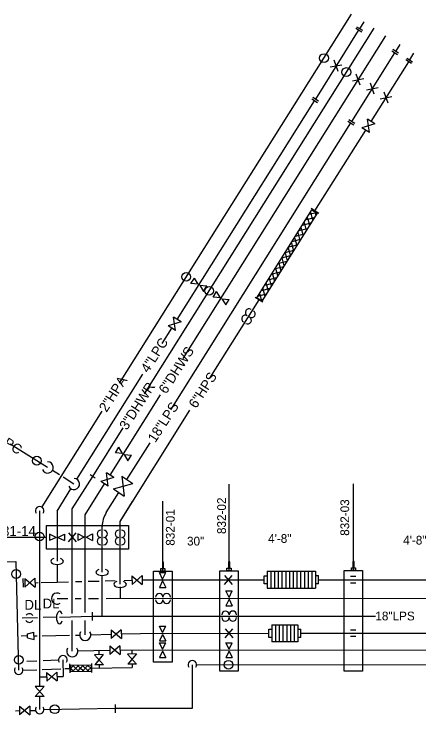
# Model space of a CAD drawing. Extents: x 9888 to 10178, y 10284 to 10314.
# Drawn here: x 9944.72 to 9960.12, y 10286.96 to 10313.63 of the extents above; entities that cross this region are included whole.
import ezdxf

# ---------------------------------------------------------------- set-up
doc = ezdxf.new("R2010")
doc.units = 0
for name, color, linetype in [('Level 51', 7, 'Continuous'), ('Level 52', 7, 'Continuous'), ('Level 53', 7, 'Continuous'), ('Level 54', 7, 'Continuous'), ('Level 55', 7, 'Continuous'), ('M-EQPM-N', 7, 'Continuous'), ('M-PROC-PIPE', 7, 'Continuous'), ('M-STEM-CONP', 7, 'Continuous'), ('M-STEM-CONP-N', 7, 'Continuous'), ('P-CMPA-PIPE', 7, 'Continuous'), ('P-CMPA-PIPE-N', 7, 'Continuous'), ('P-DOMW-HPIP', 7, 'Continuous'), ('P-DOMW-HPIP-N', 7, 'Continuous')]:
    doc.layers.add(name, color=color, linetype=linetype)

msp = doc.modelspace()

# ---------------------------------------------------------------- linework, layer by layer
at = {"layer": 'Level 51'}
for p, q in [((9956.19, 10310.392), (9957.823, 10312.996)), ((9957.942, 10312.935), (9957.721, 10313.073)), ((9957.979, 10312.994), (9957.758, 10313.132)), ((9956.745, 10311.614), (9957.186, 10311.696)), ((9957.04, 10311.444), (9956.891, 10311.866)), ((9956.043, 10310.403), (9956.264, 10310.264)), ((9956.08, 10310.462), (9956.3, 10310.323)), ((9951.069, 10301.918), (9950.786, 10302.096)), ((9950.862, 10301.59), (9950.786, 10302.096)), ((9951.069, 10301.918), (9950.579, 10301.767)), ((9950.35, 10301.088), (9950.721, 10301.678)), ((9950.862, 10301.59), (9950.579, 10301.767)), ((9947.113, 10295.926), (9949.622, 10299.926)), ((9945.996, 10296.374), (9944.576, 10297.265)), ((9946.444, 10296.094), (9946.178, 10296.26)), ((9946.999, 10295.745), (9946.593, 10296)), ((9946.355, 10294.718), (9946.885, 10295.564)), ((9946.355, 10294.718), (9946.355, 10292.806)), ((9946.319, 10293.716), (9946.071, 10293.84)), ((9946.071, 10293.84), (9946.071, 10293.592)), ((9946.389, 10293.716), (9946.636, 10293.84)), ((9946.636, 10293.84), (9946.636, 10293.592)), ((9946.319, 10293.716), (9946.071, 10293.592)), ((9946.389, 10293.716), (9946.636, 10293.592)), ((9946.355, 10292.686), (9946.355, 10292.012)), ((9949.203, 10292.252), (9949.209, 10291.918)), ((9949.203, 10292.252), (9949.597, 10291.924)), ((9949.592, 10292.258), (9949.209, 10291.918)), ((9949.592, 10292.258), (9949.597, 10291.924)), ((9950.37, 10292.128), (9950.246, 10292.376)), ((9950.246, 10292.376), (9950.494, 10292.376)), ((9950.37, 10292.128), (9950.494, 10292.376)), ((9952.72, 10291.926), (9953.012, 10292.266)), ((9952.72, 10292.266), (9953.012, 10291.926)), ((9954.229, 10291.943), (9954.229, 10292.257)), ((9954.229, 10292.257), (9954.336, 10292.257)), ((9954.34, 10292.423), (9956.184, 10292.424)), ((9954.34, 10292.423), (9954.34, 10291.777)), ((9954.482, 10292.423), (9954.482, 10291.777)), ((9954.624, 10292.423), (9954.624, 10291.777)), ((9954.765, 10292.423), (9954.765, 10291.777)), ((9954.907, 10292.423), (9954.907, 10291.777)), ((9955.049, 10292.423), (9955.049, 10291.777)), ((9955.191, 10292.423), (9955.191, 10291.777)), ((9955.333, 10292.423), (9955.333, 10291.777)), ((9955.475, 10292.423), (9955.475, 10291.777)), ((9955.617, 10292.423), (9955.617, 10291.777)), ((9955.759, 10292.423), (9955.759, 10291.777)), ((9955.901, 10292.423), (9955.901, 10291.777)), ((9956.042, 10292.423), (9956.042, 10291.777)), ((9956.184, 10292.424), (9956.184, 10291.779)), ((9956.184, 10292.423), (9956.184, 10291.777)), ((9956.184, 10292.259), (9956.292, 10292.259)), ((9956.292, 10291.944), (9956.292, 10292.259)), ((9956.292, 10292.097), (9956.292, 10292.259)), ((9957.518, 10292.237), (9957.722, 10292.237)), ((9945.059, 10292.152), (9945.065, 10291.818)), ((9945.125, 10292.152), (9945.13, 10291.818)), ((9945.125, 10292.152), (9945.519, 10291.824)), ((9945.513, 10292.158), (9945.13, 10291.818)), ((9945.513, 10292.158), (9945.519, 10291.824)), ((9945.515, 10291.991), (9945.634, 10291.994)), ((9945.753, 10291.997), (9946.355, 10292.012)), ((9946.355, 10292.012), (9946.797, 10292.024)), ((9947.058, 10292.03), (9947.301, 10292.036)), ((9947.545, 10292.043), (9947.954, 10292.053)), ((9948.184, 10292.059), (9948.567, 10292.068)), ((9948.909, 10292.077), (9949.197, 10292.084)), ((9949.594, 10292.097), (9954.229, 10292.1)), ((9950.37, 10292.059), (9950.246, 10291.811)), ((9950.37, 10292.059), (9950.494, 10291.811)), ((9954.336, 10291.943), (9954.229, 10291.943)), ((9956.292, 10291.944), (9956.184, 10291.944)), ((9956.292, 10292.101), (9971.96, 10292.111)), ((9957.518, 10291.987), (9957.722, 10291.987)), ((9950.246, 10291.811), (9950.494, 10291.811)), ((9954.34, 10291.776), (9956.184, 10291.777)), ((9946.977, 10288.841), (9946.868, 10288.729)), ((9946.967, 10288.639), (9946.868, 10288.735)), ((9947.155, 10288.642), (9946.951, 10288.841)), ((9947.166, 10288.844), (9946.967, 10288.639)), ((9947.248, 10288.738), (9947.139, 10288.844)), ((9947.155, 10288.642), (9947.248, 10288.738)), ((9947.354, 10288.847), (9947.248, 10288.738)), ((9947.248, 10288.738), (9947.344, 10288.645)), ((9947.532, 10288.647), (9947.328, 10288.846)), ((9947.543, 10288.849), (9947.344, 10288.645)), ((9947.662, 10288.708), (9947.516, 10288.849)), ((9947.661, 10288.779), (9947.532, 10288.647)), ((9946.967, 10288.639), (9946.941, 10288.613)), ((9946.993, 10288.614), (9946.967, 10288.639)), ((9947.155, 10288.642), (9947.13, 10288.616)), ((9947.181, 10288.617), (9947.155, 10288.642)), ((9947.344, 10288.645), (9947.318, 10288.619)), ((9947.37, 10288.619), (9947.344, 10288.645)), ((9947.532, 10288.647), (9947.507, 10288.621)), ((9947.559, 10288.622), (9947.532, 10288.647))]:
    msp.add_line(p, q, dxfattribs=at)
msp.add_circle((9945.585, 10296.632), 0.167, dxfattribs=at)
for centre, radius, start, end in [((9945.996, 10296.374), 0.214, 201.3711, 89.169), ((9946.999, 10295.745), 0.214, 201.3711, 89.169), ((9945.304, 10290.644), 0.164, 37.3529, 140.1974), ((9945.304, 10290.644), 0.164, 214.8908, 325.1092)]:
    msp.add_arc(centre, radius, start, end, dxfattribs=at)
msp.add_ellipse((9946.357, 10292.806), major_axis=(-0.239, 0), ratio=0.503291, start_param=5.263815, end_param=10.432096, dxfattribs=at)
at = {"layer": 'Level 52'}
for p, q in [((9957.869, 10313.064), (9958.034, 10313.327)), ((9950.925, 10302.003), (9956.142, 10310.32)), ((9951.447, 10303.372), (9951.578, 10303.582)), ((9951.722, 10303.345), (9951.578, 10303.582)), ((9951.722, 10303.345), (9951.447, 10303.372)), ((9951.781, 10303.308), (9951.925, 10303.072)), ((9951.781, 10303.308), (9952.057, 10303.282)), ((9951.925, 10303.072), (9952.057, 10303.282))]:
    msp.add_line(p, q, dxfattribs=at)
at = {"layer": 'Level 53'}
for p, q in [((9959.769, 10311.88), (9959.928, 10312.134)), ((9948.753, 10294.321), (9949.228, 10295.078))]:
    msp.add_line(p, q, dxfattribs=at)
at = {"layer": 'Level 54'}
for p, q in [((9959.873, 10311.8), (9959.652, 10311.939)), ((9958.302, 10309.542), (9959.726, 10311.811)), ((9959.836, 10311.742), (9959.615, 10311.88)), ((9958.942, 10310.233), (9958.794, 10310.655)), ((9958.648, 10310.403), (9959.088, 10310.485)), ((9958.44, 10309.447), (9958.158, 10309.625)), ((9958.234, 10309.119), (9958.158, 10309.625)), ((9958.44, 10309.447), (9957.951, 10309.296)), ((9958.234, 10309.119), (9957.951, 10309.296)), ((9956.164, 10306.133), (9958.092, 10309.207)), ((9955.943, 10306.005), (9956.209, 10306.077)), ((9955.992, 10306.083), (9956.072, 10305.783)), ((9956.308, 10306.042), (9956.017, 10306.226)), ((9956.158, 10306.108), (9956.193, 10305.976)), ((9955.89, 10305.819), (9955.813, 10305.798)), ((9955.871, 10305.89), (9955.89, 10305.819)), ((9955.89, 10305.819), (9956.136, 10305.884)), ((9955.89, 10305.819), (9955.951, 10305.59)), ((9955.684, 10305.591), (9956.006, 10305.677)), ((9955.75, 10305.697), (9955.831, 10305.396)), ((9955.425, 10305.176), (9955.747, 10305.263)), ((9955.509, 10305.311), (9955.589, 10305.01)), ((9955.554, 10305.384), (9955.877, 10305.47)), ((9955.629, 10305.504), (9955.71, 10305.203)), ((9955.295, 10304.969), (9955.617, 10305.055)), ((9955.388, 10305.117), (9955.468, 10304.817)), ((9955.146, 10304.731), (9955.227, 10304.431)), ((9955.301, 10304.798), (9955.165, 10304.762)), ((9955.267, 10304.924), (9955.301, 10304.798)), ((9955.301, 10304.798), (9955.488, 10304.848)), ((9955.301, 10304.798), (9955.348, 10304.624)), ((9955.025, 10304.538), (9955.106, 10304.238)), ((9955.036, 10304.554), (9955.358, 10304.641)), ((9954.786, 10304.142), (9955.099, 10304.226)), ((9954.905, 10304.345), (9954.985, 10304.044)), ((9954.906, 10304.347), (9955.228, 10304.434)), ((9954.647, 10303.933), (9954.668, 10303.938)), ((9954.663, 10303.959), (9954.668, 10303.938)), ((9954.668, 10303.938), (9954.969, 10304.019)), ((9954.668, 10303.938), (9954.712, 10303.777)), ((9954.776, 10304.14), (9954.786, 10304.142)), ((9954.784, 10304.152), (9954.786, 10304.142)), ((9954.786, 10304.142), (9954.864, 10303.851)), ((9954.517, 10303.725), (9954.551, 10303.734)), ((9954.551, 10303.734), (9954.542, 10303.765)), ((9954.712, 10303.777), (9954.551, 10303.734)), ((9954.551, 10303.734), (9954.623, 10303.465)), ((9954.712, 10303.777), (9954.84, 10303.812)), ((9954.712, 10303.777), (9954.744, 10303.658)), ((9954.315, 10303.326), (9954.58, 10303.397)), ((9954.387, 10303.518), (9954.433, 10303.53)), ((9954.421, 10303.572), (9954.433, 10303.53)), ((9954.433, 10303.53), (9954.71, 10303.604)), ((9954.433, 10303.53), (9954.502, 10303.272)), ((9954.128, 10303.103), (9954.197, 10303.122)), ((9954.18, 10303.186), (9954.197, 10303.122)), ((9954.197, 10303.122), (9954.451, 10303.19)), ((9954.197, 10303.122), (9954.26, 10302.886)), ((9954.258, 10303.311), (9954.315, 10303.326)), ((9954.301, 10303.379), (9954.315, 10303.326)), ((9954.315, 10303.326), (9954.381, 10303.079)), ((9953.999, 10302.896), (9954.079, 10302.918)), ((9954.059, 10302.993), (9954.079, 10302.918)), ((9954.079, 10302.918), (9954.321, 10302.983)), ((9954.079, 10302.918), (9954.122, 10302.757)), ((9952.168, 10299.766), (9954.038, 10302.747)), ((9954.175, 10302.658), (9953.884, 10302.842)), ((9954.122, 10302.757), (9954.079, 10302.745)), ((9954.122, 10302.757), (9954.191, 10302.775)), ((9954.122, 10302.757), (9954.135, 10302.711)), ((9948.753, 10294.321), (9951.411, 10298.558)), ((9948.753, 10294.321), (9949.228, 10295.079)), ((9948.753, 10291.93), (9948.753, 10294.321)), ((9948.753, 10291.829), (9948.753, 10291.39)), ((9946.357, 10291.386), (9946.762, 10291.387)), ((9947.046, 10291.387), (9947.278, 10291.387)), ((9947.549, 10291.387), (9947.936, 10291.388))]:
    msp.add_line(p, q, dxfattribs=at)
msp.add_lwpolyline([(9953.953, 10302.824), (9956.05, 10306.176), (9956.243, 10306.055), (9954.146, 10302.703)], close=True, dxfattribs=at)
for centre, radius, start, end in [((9953.66, 10302.269), 0.14, 59, 239), ((9953.752, 10302.214), 0.14, 239, 59), ((9953.517, 10302.029), 0.14, 59, 239), ((9953.607, 10301.975), 0.14, 239, 59), ((9948.703, 10293.851), 0.14, 90, 270), ((9948.809, 10293.851), 0.14, 270, 90), ((9948.703, 10293.571), 0.14, 90, 270), ((9948.808, 10293.571), 0.14, 270, 90), ((9946.357, 10291.386), 0.214, 56.0383, 303.8362)]:
    msp.add_arc(centre, radius, start, end, dxfattribs=at)
msp.add_ellipse((9948.753, 10291.93), major_axis=(-0.239, 0), ratio=0.503291, start_param=5.263815, end_param=10.432096, dxfattribs=at)
at = {"layer": 'Level 55'}
for p, q in [((9949.682, 10299.174), (9958.41, 10313.087)), ((9947.712, 10296.033), (9948.87, 10297.879))]:
    msp.add_line(p, q, dxfattribs=at)
for centre in [(9952.138, 10303.096), (9944.798, 10292.32), (9944.899, 10289.058)]:
    msp.add_circle(centre, 0.167, dxfattribs=at)
at = {"layer": 'M-EQPM-N'}
for p, q in [((9952.895, 10292.447), (9952.895, 10295.742)), ((9957.624, 10292.454), (9957.624, 10295.748)), ((9950.381, 10292.435), (9950.381, 10295.086)), ((9945.961, 10294.168), (9949.073, 10294.168)), ((9945.961, 10293.261), (9945.961, 10294.168)), ((9949.073, 10294.168), (9949.073, 10293.261)), ((9945.961, 10293.714), (9943.913, 10293.714)), ((9949.073, 10293.261), (9945.961, 10293.261))]:
    msp.add_line(p, q, dxfattribs=at)
for points in [[(9957.271, 10292.454), (9957.976, 10292.454), (9957.976, 10288.63), (9957.271, 10288.63)], [(9950.025, 10292.435), (9950.738, 10292.435), (9950.738, 10288.972), (9950.025, 10288.972)], [(9952.542, 10292.447), (9953.247, 10292.447), (9953.247, 10288.623), (9952.542, 10288.623)]]:
    msp.add_lwpolyline(points, close=True, dxfattribs=at)
at = {"layer": 'M-PROC-PIPE'}
for p, q in [((9946.936, 10294.797), (9947.712, 10296.033)), ((9947.805, 10295.973), (9947.618, 10296.092)), ((9946.936, 10290.821), (9946.936, 10294.797)), ((9946.79, 10293.544), (9947.082, 10293.884)), ((9946.79, 10293.884), (9947.082, 10293.544)), ((9943.856, 10292.776), (9944.79, 10292.799)), ((9944.79, 10292.799), (9944.895, 10288.659)), ((9946.936, 10289.382), (9946.936, 10290.553)), ((9948.361, 10289.587), (9948.366, 10289.253)), ((9948.361, 10289.587), (9948.755, 10289.259)), ((9948.749, 10289.593), (9948.366, 10289.253)), ((9948.749, 10289.593), (9948.755, 10289.259)), ((9948.115, 10289.257), (9947.781, 10289.252)), ((9948.121, 10288.869), (9947.781, 10289.252)), ((9948.115, 10289.257), (9947.788, 10288.863)), ((9947.944, 10289.414), (9947.948, 10289.254)), ((9949.374, 10289.28), (9949.04, 10289.274)), ((9949.381, 10288.891), (9949.04, 10289.274)), ((9949.374, 10289.28), (9949.047, 10288.886)), ((9949.2, 10289.426), (9949.204, 10289.277)), ((9945.784, 10288.687), (9946.495, 10288.716)), ((9946.656, 10288.72), (9946.846, 10288.724)), ((9946.849, 10288.564), (9946.844, 10288.908)), ((9947.682, 10288.576), (9947.677, 10288.919)), ((9947.68, 10288.737), (9949.217, 10288.762)), ((9948.125, 10288.869), (9947.791, 10288.863)), ((9947.958, 10288.866), (9947.961, 10288.741)), ((9949.381, 10288.891), (9949.047, 10288.886)), ((9949.214, 10288.889), (9949.217, 10288.762)), ((9945.066, 10288.667), (9945.587, 10288.68))]:
    msp.add_line(p, q, dxfattribs=at)
msp.add_lwpolyline([(9946.867, 10288.84), (9946.87, 10288.612), (9947.663, 10288.623), (9947.66, 10288.851)], close=True, dxfattribs=at)
msp.add_circle((9957.356, 10311.418), 0.167, dxfattribs=at)
for centre, radius in [((9946.936, 10289.382), 0.214), ((9944.895, 10288.659), 0.164)]:
    msp.add_arc(centre, radius, 146.0383, 33.8362, dxfattribs=at)
at = {"layer": 'M-STEM-CONP'}
for p, q in [((9959.234, 10312.204), (9959.398, 10312.466)), ((9950.678, 10298.565), (9957.526, 10309.481)), ((9949.014, 10295.911), (9949.891, 10297.31)), ((9948.824, 10296.04), (9949.238, 10295.759)), ((9948.824, 10296.04), (9948.911, 10295.277)), ((9948.497, 10295.558), (9949.238, 10295.759)), ((9948.497, 10295.558), (9948.911, 10295.277)), ((9952.896, 10291.428), (9952.772, 10291.676)), ((9952.772, 10291.676), (9953.02, 10291.676)), ((9952.896, 10291.428), (9953.02, 10291.676)), ((9948.22, 10291.388), (9973.447, 10291.406)), ((9952.896, 10291.359), (9952.772, 10291.111)), ((9952.896, 10291.359), (9953.02, 10291.111)), ((9952.772, 10291.111), (9953.02, 10291.111)), ((9945.617, 10290.655), (9945.033, 10290.635)), ((9946.321, 10290.679), (9945.828, 10290.662)), ((9947.697, 10290.708), (9946.453, 10290.666)), ((9947.697, 10290.708), (9947.696, 10290.708))]:
    msp.add_line(p, q, dxfattribs=at)
for centre, start, end in [((9950.244, 10291.442), 0, 180), ((9950.524, 10291.443), 0, 180), ((9950.244, 10291.337), 180, 0), ((9950.524, 10291.336), 180, 0)]:
    msp.add_arc(centre, 0.14, start, end, dxfattribs=at)
msp.add_ellipse((9946.453, 10290.665), major_axis=(0, 0.239), ratio=0.503291, start_param=5.263815, end_param=10.432096, dxfattribs=at)
at = {"layer": 'M-STEM-CONP-N'}
for p, q in [((9959.306, 10312.074), (9959.085, 10312.213)), ((9959.343, 10312.133), (9959.122, 10312.271)), ((9957.563, 10309.54), (9959.196, 10312.143)), ((9958.42, 10310.576), (9958.271, 10310.998)), ((9958.126, 10310.746), (9958.566, 10310.828)), ((9957.415, 10309.55), (9957.636, 10309.412)), ((9957.452, 10309.609), (9957.673, 10309.47)), ((9948.228, 10294.659), (9948.704, 10295.417)), ((9948.075, 10292.388), (9948.075, 10294.128)), ((9948.075, 10290.712), (9948.075, 10292.268)), ((9947.697, 10290.864), (9947.697, 10290.551)), ((9947.697, 10290.711), (9949.283, 10290.713)), ((9949.283, 10290.713), (9958.459, 10290.722))]:
    msp.add_line(p, q, dxfattribs=at)
for centre, radius, start, end in [((9949.075, 10294.128), 1, 147.9002, 180), ((9948.022, 10293.851), 0.14, 90, 270), ((9948.129, 10293.851), 0.14, 270, 90), ((9948.023, 10293.571), 0.14, 90, 270), ((9948.128, 10293.571), 0.14, 270, 90), ((9952.758, 10290.771), 0.14, 0, 180), ((9953.038, 10290.772), 0.14, 0, 180), ((9952.758, 10290.666), 0.14, 180, 0), ((9953.038, 10290.665), 0.14, 180, 0)]:
    msp.add_arc(centre, radius, start, end, dxfattribs=at)
msp.add_ellipse((9948.075, 10292.388), major_axis=(-0.239, 0), ratio=0.503291, start_param=5.263815, end_param=10.432096, dxfattribs=at)
at = {"layer": 'P-CMPA-PIPE'}
for p, q in [((9948.736, 10299.576), (9957.55, 10313.626)), ((9945.786, 10294.873), (9948.068, 10298.511)), ((9945.693, 10294.724), (9945.693, 10288.045)), ((9945.203, 10289.009), (9945.589, 10289.018)), ((9945.83, 10289.027), (9946.409, 10289.052)), ((9946.577, 10289.056), (9946.593, 10288.425)), ((9945.958, 10288.576), (9945.966, 10288.242)), ((9945.958, 10288.576), (9946.354, 10288.251)), ((9946.347, 10288.585), (9945.966, 10288.242)), ((9946.347, 10288.585), (9946.354, 10288.251)), ((9945.702, 10288.405), (9945.962, 10288.409)), ((9946.35, 10288.419), (9946.593, 10288.425)), ((9945.86, 10288.045), (9945.526, 10288.045)), ((9945.86, 10288.045), (9945.526, 10287.656)), ((9945.86, 10287.656), (9945.526, 10288.045)), ((9945.86, 10287.656), (9945.526, 10287.656)), ((9945.693, 10287.656), (9945.693, 10287.163)), ((9944.782, 10287.121), (9944.932, 10287.124)), ((9944.932, 10287.291), (9944.932, 10286.958)), ((9944.932, 10287.291), (9945.32, 10286.958)), ((9945.32, 10287.291), (9944.932, 10286.958)), ((9945.32, 10287.291), (9945.32, 10286.958)), ((9945.32, 10287.124), (9945.539, 10287.13)), ((9945.857, 10287.167), (9948.57, 10287.216))]:
    msp.add_line(p, q, dxfattribs=at)
for points in [[(9950.361, 10292.539), (9950.407, 10292.539), (9950.407, 10292.774), (9950.361, 10292.774)], [(9952.874, 10292.551), (9952.921, 10292.551), (9952.921, 10292.786), (9952.874, 10292.786)], [(9957.603, 10292.557), (9957.65, 10292.557), (9957.65, 10292.792), (9957.603, 10292.792)], [(9950.305, 10292.535), (9950.457, 10292.535), (9950.457, 10292.435), (9950.305, 10292.435)], [(9952.818, 10292.547), (9952.971, 10292.547), (9952.971, 10292.447), (9952.818, 10292.447)], [(9957.548, 10292.553), (9957.7, 10292.553), (9957.7, 10292.453), (9957.548, 10292.453)]]:
    msp.add_lwpolyline(points, close=True, dxfattribs=at)
for centre in [(9956.507, 10311.95), (9951.267, 10303.629), (9945.693, 10293.748), (9946.267, 10287.175)]:
    msp.add_circle(centre, 0.167, dxfattribs=at)
for centre, start, end in [((9945.693, 10294.724), 326.0383, 213.8362), ((9946.577, 10289.056), 326.0383, 213.8362), ((9945.693, 10287.163), 146.0383, 33.8362)]:
    msp.add_arc(centre, 0.164, start, end, dxfattribs=at)
at = {"layer": 'P-CMPA-PIPE-N'}
for p, q in [((9951.5, 10287.219), (9951.5, 10288.868)), ((9951.679, 10288.868), (9973.655, 10288.882)), ((9948.57, 10287.352), (9948.57, 10287.038)), ((9948.57, 10287.216), (9951.5, 10287.219))]:
    msp.add_line(p, q, dxfattribs=at)
msp.add_circle((9952.877, 10288.868), 0.167, dxfattribs=at)
msp.add_arc((9951.501, 10288.868), 0.164, 326.0383, 213.8362, dxfattribs=at)
at = {"layer": 'P-DOMW-HPIP'}
for p, q in [((9951.154, 10300.514), (9958.863, 10312.802)), ((9952.29, 10302.857), (9952.422, 10303.067)), ((9952.566, 10302.831), (9952.29, 10302.857)), ((9952.566, 10302.831), (9952.422, 10303.067)), ((9952.625, 10302.794), (9952.769, 10302.557)), ((9952.625, 10302.794), (9952.9, 10302.767)), ((9952.769, 10302.557), (9952.9, 10302.767)), ((9948.371, 10296.077), (9950.292, 10299.141)), ((9948.574, 10296.931), (9948.705, 10297.141)), ((9948.849, 10296.904), (9948.705, 10297.141)), ((9948.849, 10296.904), (9948.574, 10296.931)), ((9948.908, 10296.867), (9949.052, 10296.63)), ((9948.908, 10296.867), (9949.184, 10296.84)), ((9949.052, 10296.63), (9949.184, 10296.84)), ((9948.512, 10295.988), (9948.023, 10295.837)), ((9948.512, 10295.988), (9948.23, 10296.166)), ((9948.305, 10295.659), (9948.23, 10296.166)), ((9948.305, 10295.659), (9948.023, 10295.837))]:
    msp.add_line(p, q, dxfattribs=at)
at = {"layer": 'P-DOMW-HPIP-N'}
for p, q in [((9957.587, 10311.09), (9958.027, 10311.173)), ((9957.881, 10310.92), (9957.733, 10311.343)), ((9947.429, 10294.575), (9948.164, 10295.748)), ((9947.429, 10290.859), (9947.429, 10294.575)), ((9947.391, 10293.722), (9947.143, 10293.846)), ((9947.143, 10293.846), (9947.143, 10293.598)), ((9947.46, 10293.722), (9947.708, 10293.846)), ((9947.708, 10293.846), (9947.708, 10293.598)), ((9947.391, 10293.722), (9947.143, 10293.598)), ((9947.46, 10293.722), (9947.708, 10293.598)), ((9947.429, 10290.004), (9947.429, 10290.547)), ((9950.37, 10290.091), (9950.246, 10290.338)), ((9950.246, 10290.338), (9950.494, 10290.338)), ((9950.37, 10290.091), (9950.494, 10290.338)), ((9954.52, 10290.387), (9955.513, 10290.387)), ((9954.52, 10290.387), (9954.52, 10289.741)), ((9954.662, 10290.387), (9954.662, 10289.741)), ((9954.804, 10290.387), (9954.804, 10289.741)), ((9954.946, 10290.387), (9954.946, 10289.741)), ((9955.088, 10290.387), (9955.088, 10289.741)), ((9955.229, 10290.387), (9955.229, 10289.741)), ((9955.371, 10290.387), (9955.371, 10289.741)), ((9955.513, 10290.387), (9955.513, 10289.741)), ((9945.226, 10290.039), (9945.476, 10290.11)), ((9945.483, 10289.83), (9945.476, 10290.11)), ((9948.411, 10290.196), (9948.416, 10289.863)), ((9948.411, 10290.196), (9948.805, 10289.869)), ((9948.799, 10290.203), (9948.416, 10289.863)), ((9948.799, 10290.203), (9948.805, 10289.869)), ((9948.802, 10290.039), (9949.532, 10290.058)), ((9949.532, 10290.058), (9954.409, 10290.064)), ((9952.75, 10289.889), (9953.042, 10290.229)), ((9952.75, 10290.229), (9953.042, 10289.889)), ((9954.409, 10289.907), (9954.409, 10290.221)), ((9954.409, 10290.221), (9954.517, 10290.221)), ((9955.513, 10290.221), (9955.621, 10290.221)), ((9955.621, 10289.907), (9955.621, 10290.221)), ((9955.621, 10290.06), (9955.621, 10290.221)), ((9955.621, 10290.065), (9973.196, 10290.077)), ((9957.518, 10290.201), (9957.722, 10290.201)), ((9945.228, 10289.964), (9944.99, 10289.955)), ((9945.23, 10289.888), (9945.226, 10290.039)), ((9945.23, 10289.888), (9945.483, 10289.83)), ((9945.481, 10289.968), (9945.604, 10289.972)), ((9945.787, 10289.963), (9946.835, 10289.989)), ((9947.053, 10289.995), (9947.205, 10289.999)), ((9947.642, 10290.01), (9948.414, 10290.03)), ((9950.37, 10290.021), (9950.246, 10289.773)), ((9950.37, 10290.021), (9950.494, 10289.773)), ((9954.517, 10289.907), (9954.409, 10289.907)), ((9955.621, 10289.907), (9955.513, 10289.907)), ((9957.518, 10289.951), (9957.722, 10289.951)), ((9950.246, 10289.773), (9950.494, 10289.773)), ((9950.37, 10289.457), (9950.246, 10289.705)), ((9950.246, 10289.705), (9950.494, 10289.705)), ((9950.37, 10289.457), (9950.494, 10289.705)), ((9952.896, 10289.457), (9952.772, 10289.705)), ((9952.772, 10289.705), (9953.02, 10289.705)), ((9952.896, 10289.457), (9953.02, 10289.705)), ((9955.513, 10289.741), (9954.52, 10289.741)), ((9947.154, 10289.396), (9948.353, 10289.427)), ((9948.766, 10289.421), (9971.976, 10289.438)), ((9950.37, 10289.388), (9950.246, 10289.14)), ((9950.37, 10289.388), (9950.494, 10289.14)), ((9952.896, 10289.388), (9952.772, 10289.14)), ((9952.896, 10289.388), (9953.02, 10289.14)), ((9950.246, 10289.14), (9950.494, 10289.14)), ((9952.772, 10289.14), (9953.02, 10289.14))]:
    msp.add_line(p, q, dxfattribs=at)
msp.add_arc((9947.429, 10290.004), 0.214, 146.0383, 33.8362, dxfattribs=at)

# ---------------------------------------------------------------- texts
at = {"layer": 'Level 52'}
for s, rotation, p in [('4"LPC', 57.1519, (9949.823, 10299.946)), ('3/4"LPC', 327.4964, (9943.316, 10297.839))]:
    msp.add_text(s, height=0.375, rotation=rotation, dxfattribs=at).set_placement(p)
at = {"layer": 'Level 53'}
msp.add_text('6"HPS', height=0.375, rotation=57.1519, dxfattribs=at).set_placement((9951.647, 10298.595))
at = {"layer": 'Level 54'}
for p in [(9945.806, 10291.011), (9945.116, 10290.963)]:
    msp.add_text('DL', height=0.375, dxfattribs=at).set_placement(p)
at = {"layer": 'Level 55'}
msp.add_text('3"DHWR', height=0.375, rotation=57.1519, dxfattribs=at).set_placement((9949.011, 10297.769))
at = {"layer": 'M-EQPM-N'}
for s, p in [('832-02', (9952.778, 10293.842)), ('832-03', (9957.463, 10293.775)), ('832-01', (9950.828, 10293.397))]:
    msp.add_text(s, height=0.3333, rotation=90, dxfattribs=at).set_placement(p)
for s, height, p in [('831-14', 0.375, (9943.988, 10293.769)), ('4\'-8"', 0.3333, (9954.381, 10293.505)), ('30"', 0.3333, (9951.298, 10293.406)), ('4\'-8"', 0.3333, (9959.515, 10293.441))]:
    msp.add_text(s, height=height, dxfattribs=at).set_placement(p)
at = {"layer": 'M-STEM-CONP'}
msp.add_text('18"LPS', height=0.375, rotation=57.1519, dxfattribs=at).set_placement((9950.092, 10297.294))
at = {"layer": 'M-STEM-CONP-N'}
msp.add_text('18"LPS', height=0.3333, dxfattribs=at).set_placement((9958.459, 10290.556))
at = {"layer": 'P-CMPA-PIPE'}
msp.add_text('2"HPA', height=0.375, rotation=57.1519, dxfattribs=at).set_placement((9948.236, 10298.45))
at = {"layer": 'P-DOMW-HPIP'}
msp.add_text('6"DHWS', height=0.375, rotation=57.1519, dxfattribs=at).set_placement((9950.506, 10299.145))

doc.saveas('drawing.dxf')
